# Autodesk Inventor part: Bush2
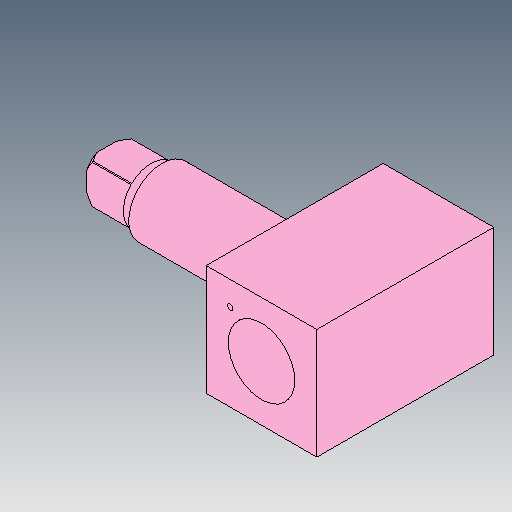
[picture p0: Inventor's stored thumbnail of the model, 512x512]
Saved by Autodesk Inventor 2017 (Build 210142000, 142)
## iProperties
Created: 2015-03
Part Number: Bush2
Document SubType Name: Modeling
Designer: Administrator
Density: 1 g/cm^3
Mass: 1.57696 g
Surface Area: 14.1373 cm^2
Volume: 1.57696 cm^3
Material: Generic
Appearance: Bubblegum
Author: Administrator
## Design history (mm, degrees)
sketch "Sketch1"
  geometry: L1 (0, 0)-(0, 3); L2 (5, 5)-(5, -5); L3 (5, -5)-(-5, -5); L4 (-5, -5)-(-5, 5); L5 (-5, 5)-(5, 5); 2 further points
  constraints: 10 end point, 2 coincident, 1 vertical, 1 vertical alignment, 12 other
  dimensions: "d0" = 3 distance of L1.start L1.end; "d5" = 10 distance of L4.end L2.start
extrude "Extrusion1" new body sketch "Sketch1" stored distance "d6" = 16; taper "d7" = 0 deg
sketch "Sketch2"
  geometry: L1 (-5, -5)-(-5, 5) reference; L2 (-5, 0)-(-17, 0); L3 (-17, 0)-(-17, 3); L4 (-17, 3)-(-6, 3); L5 (-6, 3)-(-6, 4); L6 (-6, 4)-(-5, 4); L7 (-5, 4)-(-5, 0)
  constraints: 12 end point, 3 parallel, 2 perpendicular, 1 collinear, 1 midpoint, 1 point on line
  dimensions: "d8" = 1 distance of L5.end L6.end; "d9" = 11 distance of L3.end L4.end; "d10" = 3 distance of L2.end L3.end; "d11" = 1 distance of L4.end L5.end
revolve "Revolution2" sketch "Sketch2" stored, may be unused: angle "d12" = 90 deg
sketch "Sketch3" dims "d13" = 8
  geometry: L1 (-5, 5)-(5, 5) reference; L2 (-2.828, 2.828)-(0, 0); C1 r 3 at (0, 0) reference; C2 r 0.25 at (-2.828, 2.828)
  constraints: 2 coincident, 2 end point, 1 centre point, 3 other
  dimensions: "d14" = 45 deg angle of L1 L2; "d15" = 0.5 diameter of C2
extrude "Extrusion2" cut sketch "Sketch3" distance "d16" = 20; taper "d17" = 0 deg
sketch "Sketch4"
  geometry: C1 r 3 at (0, 0) reference; C2 r 2.5 at (0, 0)
  constraints: 1 centre point
  dimensions: "d18" = 5 diameter of C2
extrude "Extrusion3" join sketch "Sketch4" distance "d19" = 5; taper "d20" = 0 deg
chamfer "Chamfer1" distance "d21" = 0.5; stored, may be unused: second distance "d22" = 2, angle "d23" = 45 deg
sketch "Sketch5"
  geometry: L1 (1.8, 1.8)-(1.8, -1.8); L2 (1.8, -1.8)-(-1.8, -1.8); L3 (-1.8, -1.8)-(-1.8, 1.8); L4 (-1.8, 1.8)-(1.8, 1.8); C1 r 2 at (0, 0) reference; C2 r 3.347 at (0, 0); 1 further point
  constraints: 8 end point, 2 coincident, 1 centre point, 9 other
  dimensions: "d24" = 3.6 distance of L3.end L1.start
extrude "Extrusion4" cut sketch "Sketch5" distance "d25" = 4; taper "d26" = 0 deg
body "Solid1"
